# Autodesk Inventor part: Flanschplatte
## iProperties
Created: 2005-05
Part Number: Flanschplatte
Material: Stahl (schweißbar)
Document SubType Name: Modeling
Designer: Mario
Manufacturer: Standard
Standards Organization: Custom
Author: Mario
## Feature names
1. Extrusion1
2. Extrusion2
3. Fase1 [Chamfer]
